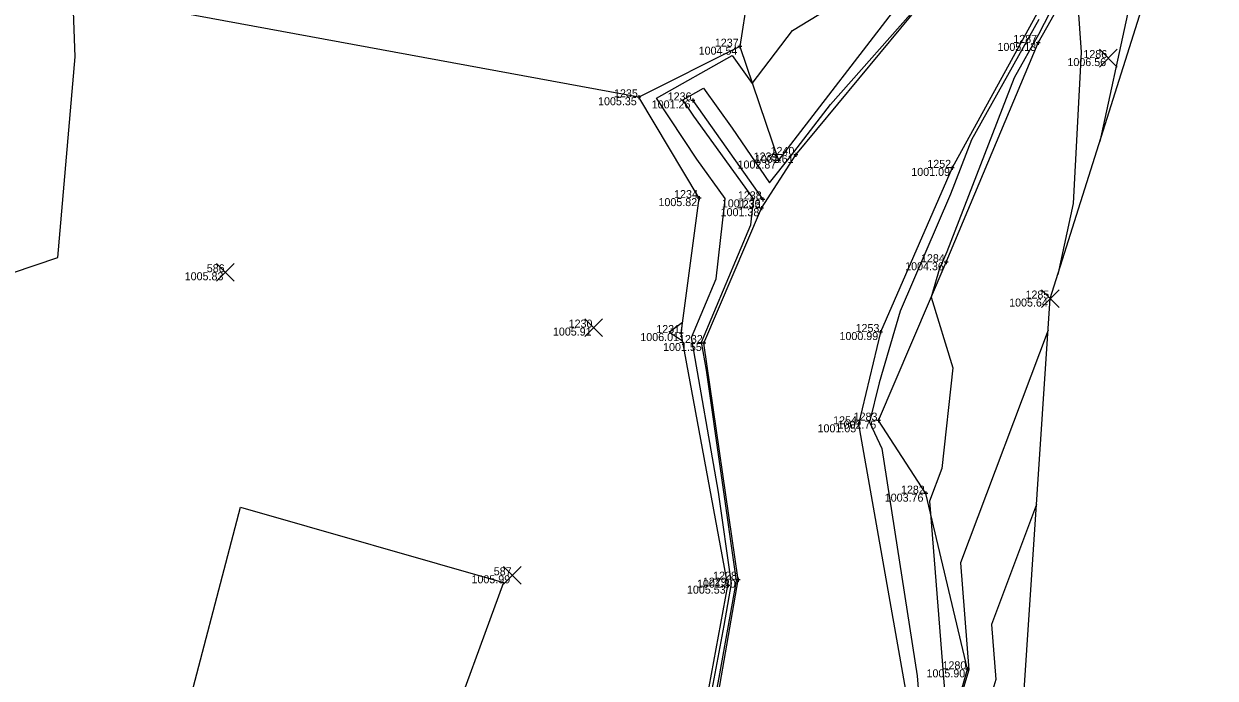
# Model space of a CAD drawing. Extents: x 2354693 to 2355622, y 637071 to 710080.
# Drawn here: x 2355435.7 to 2355614.4, y 709475.6 to 709573.6 of the extents above; entities that cross this region are included whole.
import ezdxf

# ---------------------------------------------------------------- set-up
doc = ezdxf.new("R2010")
doc.units = 0
for name, color, linetype in [('Default', 7, 'Continuous'), ('DR_X_Ditch', 7, 'Continuous'), ('DT_X_Contour_Minor', 7, 'Continuous'), ('HY_X_Water_Edge', 7, 'Continuous'), ('SV_X_Random_Point', 7, 'Continuous'), ('SV_X_Shot_Marker', 7, 'Continuous'), ('SV_X_Text_Elevation', 7, 'Continuous'), ('SV_X_Text_Name', 7, 'Continuous'), ('SV_X_Toe_of_Slope', 7, 'Continuous'), ('SV_X_Top_of_Bank', 7, 'Continuous')]:
    doc.layers.add(name, color=color, linetype=linetype)

msp = doc.modelspace()

# ---------------------------------------------------------------- linework, layer by layer
at = {"layer": 'Default'}
for points in [[(2355556.87, 709658.95), (2355543.09, 709570.18), (2355527.94, 709562.59), (2355435.81, 709579.57)], [(2355556.87, 709658.95), (2355543.09, 709570.18), (2355527.94, 709562.59), (2355435.81, 709579.57)], [(2355263.76, 708986.4), (2355330.91, 709003.61), (2355347.35, 709002.09), (2355387.45, 709051.54), (2355402.1, 709089.16), (2355425.96, 709130.16), (2355495.56, 709194.41), (2355530.33, 709221.46), (2355525, 709302.12), (2355509.66, 709318.33), (2355534.8, 709413.26), (2355566.11, 709428.47), (2355585.74, 709473.78), (2355589.64, 709532.44), (2355608.23, 709591.27)], [(2355263.76, 708986.4), (2355330.91, 709003.61), (2355347.35, 709002.09), (2355387.45, 709051.54), (2355402.1, 709089.16), (2355425.96, 709130.16), (2355495.56, 709194.41), (2355530.33, 709221.46), (2355525, 709302.12), (2355509.66, 709318.33), (2355534.8, 709413.26), (2355566.11, 709428.47), (2355585.74, 709473.78), (2355589.64, 709532.44), (2355608.23, 709591.27)]]:
    msp.add_lwpolyline(points, dxfattribs=at)
at = {"layer": 'DR_X_Ditch'}
msp.add_line((2355536.03, 709562.13), (2355546.54, 709547.3), dxfattribs=at)
at = {"layer": 'DT_X_Contour_Minor'}
for points in [[(2355600.97, 709737.27), (2355601.12, 709735.48), (2355597.4, 709671.45), (2355609.19, 709646.86), (2355607.81, 709631.74), (2355607.42, 709629.35), (2355606.75, 709620.83), (2355601.07, 709596.69), (2355598.81, 709591.11), (2355593.45, 709580.72), (2355594.25, 709569.36), (2355593.09, 709546.68), (2355590.78, 709536.05)], [(2355600.97, 709737.27), (2355601.12, 709735.48), (2355597.4, 709671.45), (2355609.19, 709646.86), (2355607.81, 709631.74), (2355607.42, 709629.35), (2355606.75, 709620.83), (2355601.07, 709596.69), (2355598.81, 709591.11), (2355593.45, 709580.72), (2355594.25, 709569.36), (2355593.09, 709546.68), (2355590.78, 709536.05)], [(2355605.79, 709715.76), (2355607.44, 709695.84), (2355605.5, 709662.4), (2355611.66, 709649.55), (2355610.07, 709632.1), (2355609.94, 709628.32), (2355608.77, 709621.18), (2355602.57, 709594.04), (2355601.22, 709575.06), (2355597.07, 709555.96)], [(2355605.79, 709715.76), (2355607.44, 709695.84), (2355605.5, 709662.4), (2355611.66, 709649.55), (2355610.07, 709632.1), (2355609.94, 709628.32), (2355608.77, 709621.18), (2355602.57, 709594.04), (2355601.22, 709575.06), (2355597.07, 709555.96)], [(2355594.68, 709585.25), (2355587.86, 709572.01), (2355584.21, 709565.49), (2355574.13, 709539.42), (2355572.99, 709536.78), (2355571.78, 709532.64), (2355575.04, 709522.08), (2355573.37, 709506.96), (2355571.53, 709502.1), (2355571.68, 709500.25), (2355573.87, 709472.48)], [(2355594.68, 709585.25), (2355587.86, 709572.01), (2355584.21, 709565.49), (2355574.13, 709539.42), (2355572.99, 709536.78), (2355571.78, 709532.64), (2355575.04, 709522.08), (2355573.37, 709506.96), (2355571.53, 709502.1), (2355571.68, 709500.25), (2355573.87, 709472.48)], [(2355538.66, 709472.29), (2355540.72, 709483.47), (2355541.84, 709489.75), (2355539.89, 709503.43), (2355535.83, 709526.6), (2355539.54, 709535.41), (2355540.85, 709546.87), (2355540.91, 709547.41), (2355536.62, 709553.34), (2355530.61, 709562.44), (2355541.92, 709568.85), (2355544.96, 709564.67), (2355550.99, 709572.6), (2355563.99, 709580.52)], [(2355538.66, 709472.29), (2355540.72, 709483.47), (2355541.84, 709489.75), (2355539.89, 709503.43), (2355535.83, 709526.6), (2355539.54, 709535.41), (2355540.85, 709546.87), (2355540.91, 709547.41), (2355536.62, 709553.34), (2355530.61, 709562.44), (2355541.92, 709568.85), (2355544.96, 709564.67), (2355550.99, 709572.6), (2355563.99, 709580.52)], [(2355407.1, 709527.21), (2355440.82, 709538.59), (2355443.41, 709568.67), (2355443.07, 709578.23)], [(2355407.1, 709527.21), (2355440.82, 709538.59), (2355443.41, 709568.67), (2355443.07, 709578.23)], [(2355539.35, 709472.2), (2355539.99, 709475.69), (2355542.57, 709490.17), (2355538.09, 709521.71), (2355537.35, 709525.93), (2355544.75, 709543.49), (2355545.06, 709546.19), (2355545.18, 709547.33), (2355536.19, 709559.75), (2355534.56, 709562.21), (2355537.62, 709563.95), (2355541.96, 709557.97), (2355547.54, 709549.76), (2355550.66, 709553.7), (2355556.66, 709561.53), (2355570.22, 709576.8)], [(2355539.35, 709472.2), (2355539.99, 709475.69), (2355542.57, 709490.17), (2355538.09, 709521.71), (2355537.35, 709525.93), (2355544.75, 709543.49), (2355545.06, 709546.19), (2355545.18, 709547.33), (2355536.19, 709559.75), (2355534.56, 709562.21), (2355537.62, 709563.95), (2355541.96, 709557.97), (2355547.54, 709549.76), (2355550.66, 709553.7), (2355556.66, 709561.53), (2355570.22, 709576.8)], [(2355587.9, 709574.25), (2355577.82, 709556.22), (2355574.68, 709548.09), (2355567.11, 709530.55), (2355563.99, 709519.81), (2355562.54, 709513.91), (2355564.39, 709509.96), (2355569.68, 709475.93), (2355570.32, 709467.83)], [(2355587.9, 709574.25), (2355577.82, 709556.22), (2355574.68, 709548.09), (2355567.11, 709530.55), (2355563.99, 709519.81), (2355562.54, 709513.91), (2355564.39, 709509.96), (2355569.68, 709475.93), (2355570.32, 709467.83)], [(2355534.33, 709527.33), (2355534.5, 709528.83), (2355532.53, 709527.38), (2355534.5, 709526.12), (2355534.3, 709527.27), (2355534.33, 709527.33)], [(2355534.33, 709527.33), (2355534.5, 709528.83), (2355532.53, 709527.38), (2355534.5, 709526.12), (2355534.3, 709527.27), (2355534.33, 709527.33)], [(2355589.32, 709527.69), (2355576.17, 709492.86), (2355577.44, 709476.81), (2355573.15, 709462.53)], [(2355589.32, 709527.69), (2355576.17, 709492.86), (2355577.44, 709476.81), (2355573.15, 709462.53)], [(2355458.98, 709465.95), (2355468.21, 709501.21), (2355507.67, 709489.91), (2355498.5, 709464.94), (2355475.74, 709456.8), (2355463.93, 709453.92), (2355457.97, 709451.38), (2355458.98, 709465.95)], [(2355458.98, 709465.95), (2355468.21, 709501.21), (2355507.67, 709489.91), (2355498.5, 709464.94), (2355475.74, 709456.8), (2355463.93, 709453.92), (2355457.97, 709451.38), (2355458.98, 709465.95)], [(2355587.59, 709501.58), (2355580.8, 709483.62), (2355581.46, 709475.35), (2355578.77, 709466.39), (2355572.26, 709455.5), (2355563.48, 709441.19), (2355557.75, 709434.69), (2355546.26, 709429.21), (2355544.93, 709429.44), (2355542.14, 709428.27), (2355540.54, 709420.87), (2355540.17, 709419.68), (2355536.57, 709414.12)], [(2355587.59, 709501.58), (2355580.8, 709483.62), (2355581.46, 709475.35), (2355578.77, 709466.39), (2355572.26, 709455.5), (2355563.48, 709441.19), (2355557.75, 709434.69), (2355546.26, 709429.21), (2355544.93, 709429.44), (2355542.14, 709428.27), (2355540.54, 709420.87), (2355540.17, 709419.68), (2355536.57, 709414.12)]]:
    msp.add_lwpolyline(points, dxfattribs=at)
at = {"layer": 'HY_X_Water_Edge'}
for points in [[(2355444.84, 709409.8), (2355493.39, 709446.46), (2355518.03, 709448.34), (2355539.67, 709472.16), (2355542.83, 709490.32), (2355537.69, 709525.78), (2355546.35, 709545.98), (2355551.46, 709553.96), (2355570.39, 709576.73), (2355584.11, 709603.77), (2355585.55, 709628.29), (2355564.78, 709662.12), (2355552.11, 709684.77), (2355549.62, 709715.93), (2355559.81, 709748.25), (2355589.77, 709771.03)], [(2355601.98, 709641.84), (2355600.27, 709603.87), (2355587.93, 709575.67), (2355574.93, 709552.02), (2355564.16, 709527.42), (2355560.86, 709513.6), (2355569.23, 709466.41), (2355552.57, 709436.48), (2355543.58, 709440.01), (2355530.89, 709431.5), (2355507.81, 709418.76), (2355493.48, 709407.24), (2355475.84, 709401.85), (2355468.12, 709405.11), (2355452.68, 709393.73)]]:
    msp.add_lwpolyline(points, dxfattribs=at)
at = {"layer": 'SV_X_Random_Point'}
for p, q in [((2355597.03, 709567.13), (2355599.69, 709569.8)), ((2355597.03, 709569.8), (2355599.69, 709567.13)), ((2355464.62, 709535.04), (2355467.29, 709537.71)), ((2355464.62, 709537.71), (2355467.29, 709535.04)), ((2355588.31, 709531.1), (2355590.97, 709533.77)), ((2355588.31, 709533.77), (2355590.97, 709531.1)), ((2355519.85, 709526.75), (2355522.52, 709529.42)), ((2355519.85, 709529.42), (2355522.52, 709526.75)), ((2355507.64, 709489.65), (2355510.31, 709492.32)), ((2355507.64, 709492.32), (2355510.31, 709489.65))]:
    msp.add_line(p, q, dxfattribs=at)
at = {"layer": 'SV_X_Shot_Marker'}
for p, q in [((2355587.83, 709571.04), (2355587.83, 709570.44)), ((2355543.39, 709570.18), (2355542.79, 709570.18)), ((2355543.09, 709570.48), (2355543.09, 709569.88)), ((2355588.13, 709570.74), (2355587.53, 709570.74)), ((2355528.24, 709562.59), (2355527.64, 709562.59)), ((2355527.94, 709562.9), (2355527.94, 709562.29)), ((2355536.33, 709562.13), (2355535.73, 709562.13)), ((2355536.03, 709562.43), (2355536.03, 709561.83)), ((2355549.19, 709553.12), (2355548.59, 709553.12)), ((2355548.89, 709553.42), (2355548.89, 709552.82)), ((2355551.76, 709553.96), (2355551.16, 709553.96)), ((2355551.46, 709554.26), (2355551.46, 709553.66)), ((2355575.23, 709552.02), (2355574.63, 709552.02)), ((2355574.93, 709552.32), (2355574.93, 709551.72)), ((2355537.01, 709547.79), (2355537.01, 709547.19)), ((2355537.31, 709547.49), (2355536.71, 709547.49)), ((2355546.65, 709545.98), (2355546.05, 709545.98)), ((2355546.84, 709547.3), (2355546.24, 709547.3)), ((2355546.35, 709546.28), (2355546.35, 709545.68)), ((2355546.54, 709547.6), (2355546.54, 709547)), ((2355574.33, 709537.88), (2355573.73, 709537.88)), ((2355574.03, 709538.18), (2355574.03, 709537.58)), ((2355534.59, 709527.27), (2355533.99, 709527.27)), ((2355534.29, 709527.57), (2355534.29, 709526.97)), ((2355564.46, 709527.42), (2355563.86, 709527.42)), ((2355564.16, 709527.72), (2355564.16, 709527.12)), ((2355537.99, 709525.78), (2355537.39, 709525.78)), ((2355537.69, 709526.08), (2355537.69, 709525.48)), ((2355560.86, 709513.9), (2355560.86, 709513.3)), ((2355564.17, 709514.15), (2355563.57, 709514.15)), ((2355563.87, 709514.45), (2355563.87, 709513.85)), ((2355561.16, 709513.6), (2355560.56, 709513.6)), ((2355571.27, 709503.21), (2355570.67, 709503.21)), ((2355570.97, 709503.51), (2355570.97, 709502.91)), ((2355542.83, 709490.62), (2355542.83, 709490.02)), ((2355541.57, 709489.43), (2355540.97, 709489.43)), ((2355541.27, 709489.73), (2355541.27, 709489.13)), ((2355543.13, 709490.32), (2355542.53, 709490.32)), ((2355577.54, 709476.89), (2355576.94, 709476.89)), ((2355577.24, 709477.19), (2355577.24, 709476.59))]:
    msp.add_line(p, q, dxfattribs=at)
at = {"layer": 'SV_X_Toe_of_Slope'}
for points in [[(2355444.84, 709409.8), (2355493.39, 709446.46), (2355518.03, 709448.34), (2355539.67, 709472.16), (2355542.83, 709490.32), (2355537.69, 709525.78), (2355546.35, 709545.98), (2355551.46, 709553.96), (2355570.39, 709576.73), (2355584.11, 709603.77), (2355585.55, 709628.29), (2355564.78, 709662.12), (2355552.11, 709684.77), (2355549.62, 709715.93), (2355559.81, 709748.25), (2355589.77, 709771.03)], [(2355601.98, 709641.84), (2355600.27, 709603.87), (2355587.93, 709575.67), (2355574.93, 709552.02), (2355564.16, 709527.42), (2355560.86, 709513.6), (2355569.23, 709466.41), (2355552.57, 709436.48), (2355543.58, 709440.01), (2355530.89, 709431.5), (2355507.81, 709418.76), (2355493.48, 709407.24), (2355475.84, 709401.85), (2355468.12, 709405.11), (2355452.68, 709393.73)]]:
    msp.add_lwpolyline(points, dxfattribs=at)
at = {"layer": 'SV_X_Top_of_Bank'}
for points in [[(2355543.09, 709570.18), (2355548.89, 709553.12), (2355567.83, 709577.76), (2355580.58, 709604.58), (2355583.21, 709626.8), (2355561.61, 709661.42)], [(2355539.65, 709419.5), (2355536.88, 709428.91), (2355545.13, 709427.91), (2355562.31, 709433.11), (2355572.18, 709444.95), (2355572.3, 709459.52), (2355577.24, 709476.89), (2355570.97, 709503.21), (2355563.87, 709514.15), (2355574.03, 709537.88), (2355587.83, 709570.74), (2355601.3, 709594.65), (2355608.86, 709626.36), (2355614.36, 709652.49)], [(2355442.68, 709412.53), (2355487.57, 709449.77), (2355516.94, 709455.25), (2355538.12, 709472.36), (2355541.27, 709489.43), (2355534.29, 709527.27), (2355537.01, 709547.49), (2355527.94, 709562.59)]]:
    msp.add_lwpolyline(points, dxfattribs=at)

# ---------------------------------------------------------------- texts
at = {"layer": 'SV_X_Text_Elevation'}
for s, p in [('1004.54', (2355536.92, 709568.98)), ('1005.13', (2355581.72, 709569.54)), ('1006.56', (2355592.21, 709567.27)), ('1005.35', (2355521.83, 709561.4)), ('1001.26', (2355529.88, 709560.93)), ('1002.87', (2355542.75, 709551.92)), ('1001.61', (2355545.34, 709552.76)), ('1001.09', (2355568.8, 709550.82)), ('1005.82', (2355530.89, 709546.29)), ('1001.38', (2355540.21, 709544.78)), ('1001.36', (2355540.39, 709546.1)), ('1004.36', (2355567.88, 709536.68)), ('1005.83', (2355459.85, 709535.18)), ('1005.64', (2355583.47, 709531.24)), ('1005.91', (2355515.06, 709526.89)), ('1006.01', (2355528.17, 709526.07)), ('1000.99', (2355558.03, 709526.22)), ('1001.55', (2355531.58, 709524.58)), ('1002.75', (2355557.75, 709512.95)), ('1001.05', (2355554.74, 709512.4)), ('1003.76', (2355564.82, 709502.01)), ('1005.99', (2355502.85, 709489.78)), ('1005.53', (2355535.16, 709488.23)), ('1001.30', (2355536.67, 709489.12)), ('1005.90', (2355571.08, 709475.69))]:
    msp.add_text(s, height=1.2, dxfattribs=at).set_placement(p)
at = {"layer": 'SV_X_Text_Name'}
for s, p in [('1237', (2355539.34, 709570.18)), ('1287', (2355584.09, 709570.74)), ('1286', (2355594.6, 709568.47)), ('1235', (2355524.22, 709562.59)), ('1236', (2355532.27, 709562.13)), ('1240', (2355547.7, 709553.96)), ('1239', (2355545.16, 709553.12)), ('1252', (2355571.2, 709552.02)), ('1234', (2355533.23, 709547.49)), ('1238', (2355542.79, 709547.3)), ('1233', (2355542.64, 709545.98)), ('1284', (2355570.25, 709537.88)), ('586', (2355463.16, 709536.38)), ('1285', (2355585.92, 709532.44)), ('1230', (2355517.42, 709528.09)), ('1231', (2355530.56, 709527.27)), ('1253', (2355560.44, 709527.42)), ('1232', (2355533.96, 709525.78)), ('1254', (2355557.08, 709513.6)), ('1283', (2355560.15, 709514.15)), ('1282', (2355567.25, 709503.21)), ('587', (2355506.19, 709490.98)), ('1229', (2355537.54, 709489.43)), ('1228', (2355539.08, 709490.32)), ('1280', (2355573.48, 709476.89))]:
    msp.add_text(s, height=1.2, dxfattribs=at).set_placement(p)

doc.saveas('drawing.dxf')
